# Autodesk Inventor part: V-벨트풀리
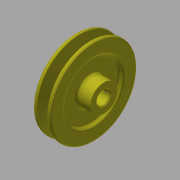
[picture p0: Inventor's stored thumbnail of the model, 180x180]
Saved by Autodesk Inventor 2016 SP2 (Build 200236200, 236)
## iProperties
Created: 2015-09
Part Number: V-벨트풀리
Material: 강철, 연강
Document SubType Name: Modeling
Designer: mduedu
Density: 7.86 g/cm^3
Mass: 779.014 g
Surface Area: 277.465 cm^2
Volume: 99.1112 cm^3
Appearance: 강철
Author: mduedu
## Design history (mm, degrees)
sketch "스케치1"
  geometry: L1 (-10, 0)-(10, 0); L2 (-10, 0)-(-10, 48); L3 (-10, 48)-(-5.976, 48); L4 (-5.976, 48)-(-2.154, 35.5); L5 (-2.154, 35.5)-(2.154, 35.5); L6 (2.154, 35.5)-(5.976, 48); L7 (5.976, 48)-(10, 48); L8 (10, 48)-(10, 0); L9 (0, 0)-(0, 35.5); L10 (-10, 43.5)-(10, 43.5); 3 further points
  constraints: 20 end point, 6 point on line, 3 perpendicular, 2 midpoint, 2 parallel, 2 symmetric about line, 1 coincident, 1 collinear, 1 equal length, 1 horizontal, 1 vertical, 1 vertical alignment
  dimensions: "d0" = 20 distance between parallel lines of L8 L2; "d2" = 96 diameter of L3 L1; "d3" = 87 diameter of L10 L1; "d4" = 4.5 distance between parallel lines of L10 L3 (derived); "d5" = 8 distance between parallel lines of L5 L10; "d6" = 9.2 distance of point (4.6, 43.5) point (-4.6, 43.5); "d7" = 34 deg angle of L6 L4
revolve "회전1" sketch "스케치1" stored, may be unused: angle "d8" = 90 deg
sketch "스케치2"
  geometry: C1 r 15 at (0, 0); 1 further point
  constraints: 1 centre point, 1 coincident
  dimensions: "d9" = 30 diameter of C1
extrude "돌출1" join sketch "스케치2" distance "d10" = 11; taper "d11" = 0 deg
fillet "모깎기1" dims "d12" = 1, "d13" = 0.5, "d14" = 2
sketch "스케치3"
  geometry: C1 r 15 at (0, 0) reference; C2 r 32 at (0, 0); 1 further point
  constraints: 1 centre point, 1 coincident
  dimensions: "d15" = 64 diameter of C2
extrude "돌출2" cut sketch "스케치3" distance "d16" = 4; taper "d17" = 0 deg
fillet "모깎기2" dims "d18" = 3
fillet "모깎기3" dims "d19" = 3
fillet "모깎기4" dims "d20" = 3
sketch "스케치4"
  geometry: C1 r 7.5 at (0, 0); 1 further point
  constraints: 1 centre point, 1 coincident
  dimensions: "d21" = 15 diameter of C1
extrude "돌출3" cut sketch "스케치4" stored distance "d22" = 4; taper "d23" = 0 deg
sketch "스케치5"
  geometry: L1 (-2.5, 7.071)-(2.5, 7.071); L2 (2.5, 7.071)-(2.5, 9.8); L3 (2.5, 9.8)-(-2.5, 9.8); L4 (-2.5, 9.8)-(-2.5, 7.071); A1 r 7.5 centre (0, 0) between (-2.5, 7.071) and (2.5, 7.071) reference; 2 further points
  constraints: 8 end point, 3 point on circle, 2 parallel, 1 horizontal, 1 perpendicular, 1 vertical alignment
  dimensions: "d24" = 5 distance of L2.end L3.end; "d26" = 17.3 distance from line of L3 point (0, -7.5)
extrude "돌출4" cut sketch "스케치5" stored distance "d27" = 4; taper "d28" = 0 deg
chamfer "모따기1" distance "d29" = 1; stored, may be unused: second distance "d30" = 2, angle "d31" = 45 deg
node "작업 평면1"
sketch "스케치6"
  geometry: L1 (-11, 15)-(-11, -15) reference; 2 further points
  constraints: 1 horizontal alignment
  dimensions: "d32" = 5 distance from line of point (-6, 0) L1
hole "구멍1" sketch "스케치6" at (-6, 0) diameter "d33" = 3.242; stored, may be unused: countersink angle "d37" = 90 deg, drill point angle "d39" = 118 deg; dims "d34" = 6, "d35" = 4, "d36" = 2, "d38" = 8
node "솔리드1"
mirror "대칭1"
